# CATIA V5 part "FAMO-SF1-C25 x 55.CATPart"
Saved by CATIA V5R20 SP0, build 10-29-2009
Part number: FAMO-SF1-C25 x 55
Definition: NONE
Nomenclature: FAMO-SF1-C25 x 55
Source: Unknown
Description: FAMO-SF1-C25 x 55
Bounding box of the stored display mesh (mm): x -32 to 23, y -22 to 22, z -22 to 22
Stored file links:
  C:\Users\Utente\Desktop\IO LAVORO\3D X SITO CF\X SITO\FAMO\FAMO-SF1-C25 x 55.CATPart

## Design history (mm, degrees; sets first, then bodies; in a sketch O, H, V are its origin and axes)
Body1 "FAMO-SF1-C25 x 55" (main body)
  Solid1: solid without history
